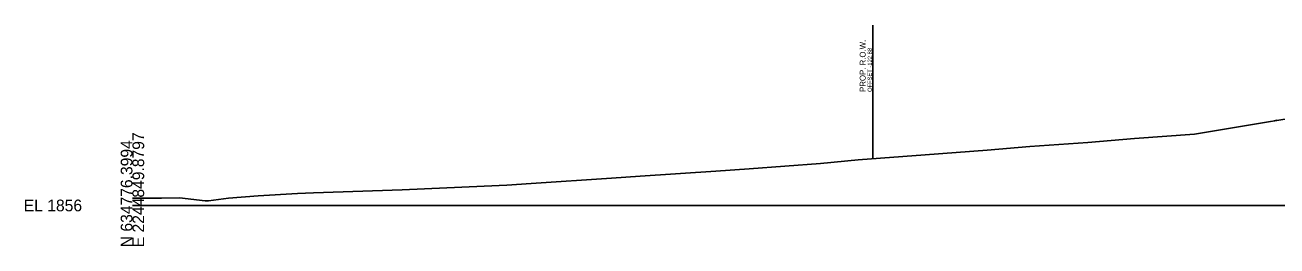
# Model space of a CAD drawing. Extents: x -26 to 669, y -22 to 6560.
# Drawn here: x -25.7 to 273.8, y 2490.3 to 2543.2 of the extents above; entities that cross this region are included whole.
import ezdxf

# ---------------------------------------------------------------- set-up
doc = ezdxf.new("R2010")
doc.units = 0
for name, color, linetype in [('DESIGN - ROW - Right-of-Way and Easement Labels', 7, 'Continuous'), ('DESIGN - ROW - Right-of-Way Linework', 7, 'Continuous'), ('DESIGN - SHEET - Light Grid', 7, 'Continuous'), ('DESIGN - TYPICAL - Finished Grade and Subgrade', 7, 'Continuous'), ('SURVEY - GROUND - Top of Ground', 7, 'Continuous')]:
    doc.layers.add(name, color=color, linetype=linetype)

msp = doc.modelspace()

# ---------------------------------------------------------------- linework, layer by layer
at = {"layer": 'DESIGN - ROW - Right-of-Way Linework'}
msp.add_line((177.12, 2511.16), (177.12, 2543.16), dxfattribs=at)
at = {"layer": 'DESIGN - SHEET - Light Grid'}
msp.add_line((0, 2500), (300, 2500), dxfattribs=at)
at = {"layer": 'DESIGN - TYPICAL - Finished Grade and Subgrade'}
msp.add_line((273.19, 2520.21), (273.77, 2520.41), dxfattribs=at)
at = {"layer": 'SURVEY - GROUND - Top of Ground'}
for p, q in [((271.26, 2519.9), (254.02, 2517.05)), ((280.1, 2521.35), (271.26, 2519.9))]:
    msp.add_line(p, q, dxfattribs=at)
msp.add_lwpolyline([(0, 2501.73), (6.91, 2501.74), (11.28, 2501.8), (17.36, 2501.11), (17.71, 2501.07), (18.17, 2501.12), (22.95, 2501.72), (30.08, 2502.27), (39.5, 2502.88), (43.27, 2503), (64.52, 2503.76), (84.14, 2504.59), (89.54, 2504.88), (95.39, 2505.25), (114.55, 2506.51), (121.46, 2507.02), (139.58, 2508.17), (147.54, 2508.75), (164.6, 2510.05), (173.61, 2510.89), (189.63, 2512.13), (204.42, 2513.25), (214.64, 2514.14), (228.49, 2515.07), (239.66, 2515.98), (254.02, 2517.05)], dxfattribs=at)

# ---------------------------------------------------------------- texts
at = {"layer": 'DESIGN - ROW - Right-of-Way and Easement Labels'}
for s, height, p in [('PROP. R.O.W.', 1.4, (175.37, 2527.16)), ('OFFSET -122.88', 1, (176.87, 2527.16))]:
    msp.add_text(s, height=height, rotation=90, dxfattribs=at).set_placement(p)
at = {"layer": 'DESIGN - SHEET - Light Grid'}
for s, p in [('N 634776.3994', (0, 2490)), ('E 2244849.8797', (2.8, 2490))]:
    msp.add_text(s, height=2.8, rotation=90, dxfattribs=at).set_placement(p)
msp.add_text('EL 1856', height=2.8, dxfattribs=at).set_placement((-26, 2498.6))

doc.saveas('drawing.dxf')
